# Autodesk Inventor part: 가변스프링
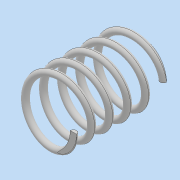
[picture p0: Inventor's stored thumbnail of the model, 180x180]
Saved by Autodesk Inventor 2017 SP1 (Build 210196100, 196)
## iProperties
Part Number: 가변스프링
Material: 일반
Document SubType Name: Modeling
Designer: MRC
Density: 1 g/cm^3
Appearance: 기본값
Author: MRC
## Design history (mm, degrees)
sketch "스케치1"
  geometry: L1 (0, 0)-(9, 0); L2 (0, 0)-(0, 28.5); L3 (0, 28.5)-(9, 28.5); C1 r 1 at (9, 0)
  constraints: 6 end point, 2 horizontal, 1 centre point, 1 coincident, 1 vertical
  dimensions: "d0" = 9 distance of L1.start L1.end; "d1" = 28.49998 distance of L1.start L2.end (derived); "d2" = 9 distance of L2.end L3.end; "d3" = 2 diameter of C1
feature "코일1" pitch "d4" = 10; turns "d6" = 5; dims "d5" = 28.49998 (= d1), "d7" = 0, angle "d8" = 90 deg, angle "d9" = 90 deg, "d10" = 0, "d11" = 0
sketch "스케치2"
  geometry: L1 (28.5, 12.299)-(0, 12.299); L2 (0, 12.299)-(0, -12.299); L3 (0, -12.299)-(28.5, -12.299); L4 (28.5, -12.299)-(28.5, 12.299); 2 further points
  constraints: 8 end point, 2 parallel, 1 coincident, 1 horizontal, 1 midpoint, 1 perpendicular
  dimensions: "d12" = 28.49998 distance of L2.end L3.end (= d1)
extrude "돌출1" sketch "스케치2" stored distance "d13" = 0; taper "d14" = 0 deg
node "솔리드1"
